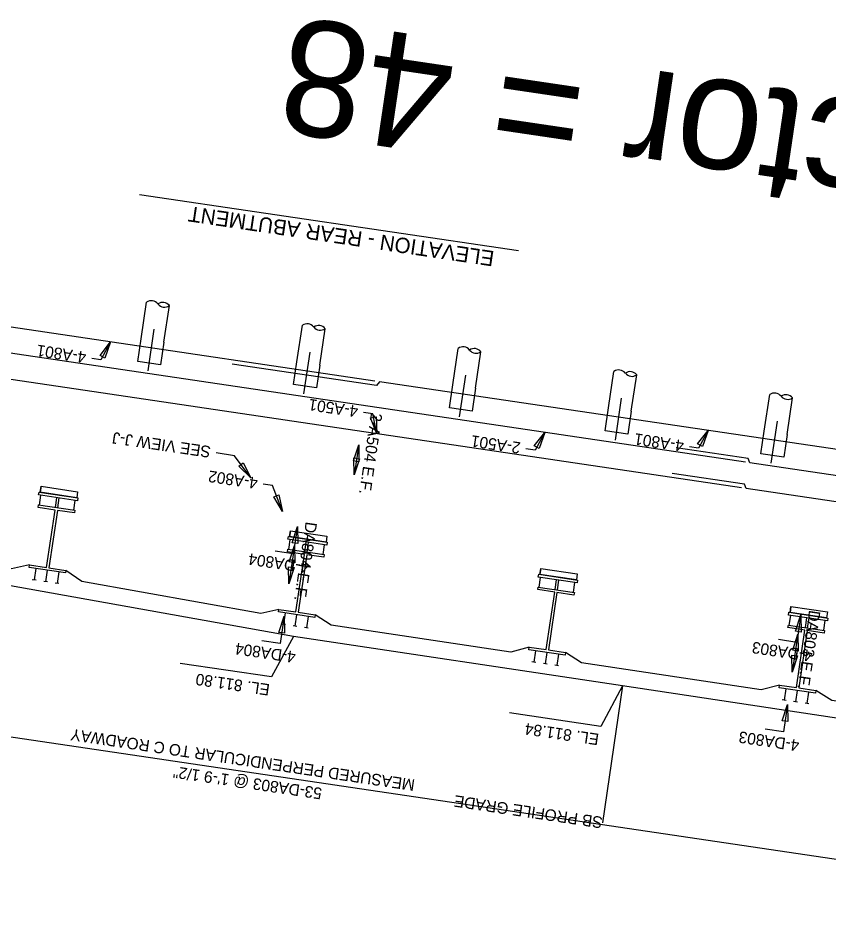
# Model space of a CAD drawing. Extents: x 1468952 to 1470054, y 573916 to 574214.
# Drawn here: x 1469014.75 to 1469049.93, y 574056.5 to 574095.95 of the extents above; entities that cross this region are included whole.
import ezdxf

# ---------------------------------------------------------------- set-up
doc = ezdxf.new("R2010")
doc.units = 0
for name, color, linetype in [('BR_P_Beam_Stl_Det', 7, 'Continuous'), ('BR_P_Gen_Phase_Construction', 7, 'Continuous'), ('BR_P_Sub_Centerline', 7, 'Continuous'), ('BR_P_Sub_Foot_Centerline', 7, 'Continuous'), ('BR_X_SV_Beam_Seat', 7, 'Continuous'), ('Default', 7, 'Continuous'), ('GE_P_CL_50', 7, 'Continuous'), ('GK_Cells', 7, 'Continuous'), ('PF_X_Ground_Line', 7, 'Continuous'), ('SV_X_Text_Elevation', 7, 'Continuous'), ('UT_X_Water', 7, 'Continuous')]:
    doc.layers.add(name, color=color, linetype=linetype)

# ---------------------------------------------------------------- blocks, each defined once
blk = doc.blocks.new('arrowOhio')
at = {"layer": 'Default'}
blk.add_lwpolyline([(0.00381, 0.000635), (0.00381, -0.000635), (0, 0)], close=True, dxfattribs=at)

msp = doc.modelspace()

# ---------------------------------------------------------------- linework, layer by layer
at = {"layer": 'BR_P_Beam_Stl_Det'}
for points in [[(1469030.229, 574080.212), (1469004.495, 574084.021), (1469004.371, 574083.865), (1468998.106, 574084.792)], [(1469046.308, 574076.694), (1469010.886, 574081.938), (1469010.812, 574082.124), (1469007.68, 574082.588)], [(1469046.144, 574075.581), (1469010.721, 574080.825), (1469010.648, 574081.011), (1469007.515, 574081.475)], [(1469056.161, 574076.372), (1469030.427, 574080.182), (1469030.303, 574080.026), (1469024.038, 574080.953)], [(1469082.126, 574071.391), (1469046.506, 574076.665), (1469046.433, 574076.85), (1469043.3, 574077.314)], [(1469081.962, 574070.278), (1469046.341, 574075.552), (1469046.268, 574075.738), (1469043.135, 574076.201)]]:
    msp.add_lwpolyline(points, dxfattribs=at)
at = {"layer": 'BR_P_Gen_Phase_Construction'}
for p, q in [((1469020.089, 574082.05), (1469020.323, 574083.632)), ((1469021.078, 574081.903), (1469021.313, 574083.486)), ((1469026.849, 574081.049), (1469027.083, 574082.632)), ((1469027.838, 574080.902), (1469028.072, 574082.485)), ((1469033.608, 574080.048), (1469033.843, 574081.631)), ((1469034.598, 574079.902), (1469034.832, 574081.484)), ((1469040.368, 574079.047), (1469040.602, 574080.63)), ((1469041.357, 574078.901), (1469041.592, 574080.484)), ((1469047.128, 574078.047), (1469047.362, 574079.629)), ((1469048.117, 574077.9), (1469048.351, 574079.483))]:
    msp.add_line(p, q, dxfattribs=at)
for centre, start, end in [((1469020.532, 574083.336), 37.976, 125.1816), ((1469021.027, 574083.263), 37.976, 125.1816), ((1469021.104, 574083.782), 217.976, 305.1816), ((1469027.292, 574082.335), 37.976, 125.1816), ((1469027.787, 574082.262), 37.976, 125.1816), ((1469027.863, 574082.782), 217.976, 305.1816), ((1469034.052, 574081.335), 37.976, 125.1816), ((1469034.546, 574081.261), 37.976, 125.1816), ((1469034.623, 574081.781), 217.976, 305.1816), ((1469040.811, 574080.334), 37.976, 125.1816), ((1469041.306, 574080.261), 37.976, 125.1816), ((1469041.383, 574080.78), 217.976, 305.1816), ((1469047.571, 574079.333), 37.976, 125.1816), ((1469048.065, 574079.26), 37.976, 125.1816), ((1469048.142, 574079.779), 217.976, 305.1816)]:
    msp.add_arc(centre, 0.362, start, end, dxfattribs=at)
at = {"layer": 'BR_P_Sub_Centerline'}
for p, q in [((1469019.943, 574081.06), (1469020.089, 574082.05)), ((1469021.078, 574081.903), (1469020.932, 574080.914)), ((1469020.932, 574080.914), (1469019.943, 574081.06)), ((1469026.702, 574080.06), (1469026.849, 574081.049)), ((1469027.838, 574080.902), (1469027.692, 574079.913)), ((1469027.692, 574079.913), (1469026.702, 574080.06)), ((1469033.462, 574079.059), (1469033.608, 574080.048)), ((1469034.598, 574079.902), (1469034.451, 574078.913)), ((1469034.451, 574078.913), (1469033.462, 574079.059)), ((1469040.222, 574078.058), (1469040.368, 574079.047)), ((1469041.357, 574078.901), (1469041.211, 574077.912)), ((1469041.211, 574077.912), (1469040.222, 574078.058)), ((1469046.981, 574077.058), (1469047.128, 574078.047)), ((1469048.117, 574077.9), (1469047.97, 574076.911)), ((1469047.97, 574076.911), (1469046.981, 574077.058))]:
    msp.add_line(p, q, dxfattribs=at)
at = {"layer": 'BR_P_Sub_Foot_Centerline'}
for p, q in [((1469015.673, 574074.836), (1469015.736, 574075.259)), ((1469016.37, 574074.733), (1469016.433, 574075.155)), ((1469016.469, 574074.718), (1469016.532, 574075.141)), ((1469017.166, 574074.615), (1469017.229, 574075.038)), ((1469026.492, 574072.911), (1469026.554, 574073.333)), ((1469027.189, 574072.808), (1469027.251, 574073.23)), ((1469027.288, 574072.793), (1469027.35, 574073.216)), ((1469027.985, 574072.69), (1469028.047, 574073.112)), ((1469037.353, 574071.273), (1469037.415, 574071.695)), ((1469038.05, 574071.17), (1469038.112, 574071.592)), ((1469038.149, 574071.155), (1469038.211, 574071.577)), ((1469038.846, 574071.052), (1469038.908, 574071.474)), ((1469048.212, 574069.625), (1469048.275, 574070.047)), ((1469048.909, 574069.521), (1469048.972, 574069.944)), ((1469049.008, 574069.507), (1469049.071, 574069.929)), ((1469049.705, 574069.404), (1469049.768, 574069.826))]:
    msp.add_line(p, q, dxfattribs=at)
at = {"layer": 'BR_X_SV_Beam_Seat'}
msp.add_line((1469040.98, 574066.988), (1469040.101, 574061.053), dxfattribs=at)
at = {"layer": 'GE_P_CL_50'}
for p, q in [((1469015.745, 574075.647), (1469015.707, 574075.389)), ((1469015.639, 574075.273), (1469015.657, 574075.397)), ((1469017.326, 574075.023), (1469015.639, 574075.273)), ((1469015.657, 574075.397), (1469017.344, 574075.147)), ((1469017.333, 574075.412), (1469017.294, 574075.154)), ((1469017.344, 574075.147), (1469017.326, 574075.023)), ((1469026.563, 574073.722), (1469026.525, 574073.464)), ((1469026.457, 574073.348), (1469026.476, 574073.471)), ((1469028.144, 574073.098), (1469026.457, 574073.348)), ((1469026.476, 574073.471), (1469028.163, 574073.222)), ((1469028.151, 574073.487), (1469028.113, 574073.229)), ((1469028.163, 574073.222), (1469028.144, 574073.098)), ((1469037.424, 574072.083), (1469037.386, 574071.826)), ((1469037.318, 574071.71), (1469037.337, 574071.833)), ((1469039.005, 574071.46), (1469037.318, 574071.71)), ((1469037.337, 574071.833), (1469039.024, 574071.583)), ((1469039.012, 574071.848), (1469038.974, 574071.591)), ((1469039.024, 574071.583), (1469039.005, 574071.46)), ((1469048.284, 574070.435), (1469048.246, 574070.178)), ((1469048.178, 574070.061), (1469048.196, 574070.185)), ((1469049.865, 574069.812), (1469048.178, 574070.061)), ((1469048.196, 574070.185), (1469049.883, 574069.935)), ((1469049.872, 574070.2), (1469049.833, 574069.943)), ((1469049.883, 574069.935), (1469049.865, 574069.812))]:
    msp.add_line(p, q, dxfattribs=at)
for points in [[(1469017.333, 574075.412), (1469017.294, 574075.154), (1469015.707, 574075.389), (1469015.745, 574075.647)], [(1469028.151, 574073.487), (1469028.113, 574073.229), (1469026.525, 574073.464), (1469026.563, 574073.722)], [(1469039.012, 574071.848), (1469038.974, 574071.591), (1469037.386, 574071.826), (1469037.424, 574072.083)], [(1469049.872, 574070.2), (1469049.833, 574069.943), (1469048.246, 574070.178), (1469048.284, 574070.435)]]:
    msp.add_lwpolyline(points, close=True, dxfattribs=at)
at = {"layer": 'GK_Cells'}
for p, q in [((1469015.615, 574074.729), (1469015.632, 574074.842)), ((1469015.632, 574074.842), (1469017.207, 574074.609)), ((1469016.353, 574074.62), (1469015.615, 574074.729)), ((1469015.984, 574072.126), (1469016.353, 574074.62)), ((1469016.453, 574074.605), (1469016.083, 574072.111)), ((1469017.191, 574074.496), (1469016.453, 574074.605)), ((1469017.207, 574074.609), (1469017.191, 574074.496)), ((1469026.434, 574072.804), (1469026.451, 574072.917)), ((1469027.172, 574072.694), (1469026.434, 574072.804)), ((1469026.451, 574072.917), (1469028.026, 574072.684)), ((1469026.803, 574070.201), (1469027.172, 574072.694)), ((1469027.271, 574072.68), (1469026.902, 574070.186)), ((1469028.009, 574072.571), (1469027.271, 574072.68)), ((1469028.026, 574072.684), (1469028.009, 574072.571)), ((1469015.229, 574072.122), (1469015.246, 574072.235)), ((1469016.805, 574071.889), (1469015.229, 574072.122)), ((1469015.246, 574072.235), (1469015.984, 574072.126)), ((1469015.522, 574072.078), (1469015.449, 574071.584)), ((1469016.017, 574072.005), (1469015.944, 574071.511)), ((1469016.083, 574072.111), (1469016.821, 574072.002)), ((1469016.821, 574072.002), (1469016.805, 574071.889)), ((1469015.532, 574071.572), (1469015.367, 574071.596)), ((1469016.512, 574071.932), (1469016.438, 574071.437)), ((1469016.026, 574071.498), (1469015.861, 574071.523)), ((1469016.521, 574071.425), (1469016.356, 574071.45)), ((1469037.295, 574071.165), (1469037.312, 574071.279)), ((1469037.312, 574071.279), (1469038.887, 574071.046)), ((1469038.033, 574071.056), (1469037.295, 574071.165)), ((1469037.664, 574068.563), (1469038.033, 574071.056)), ((1469038.132, 574071.042), (1469037.763, 574068.548)), ((1469038.87, 574070.932), (1469038.132, 574071.042)), ((1469038.887, 574071.046), (1469038.87, 574070.932)), ((1469026.048, 574070.197), (1469026.065, 574070.31)), ((1469027.623, 574069.964), (1469026.048, 574070.197)), ((1469026.065, 574070.31), (1469026.803, 574070.201)), ((1469026.341, 574070.153), (1469026.268, 574069.659)), ((1469026.836, 574070.08), (1469026.762, 574069.586)), ((1469026.902, 574070.186), (1469027.64, 574070.077)), ((1469027.64, 574070.077), (1469027.623, 574069.964)), ((1469026.35, 574069.647), (1469026.185, 574069.671)), ((1469027.33, 574070.007), (1469027.257, 574069.512)), ((1469048.154, 574069.517), (1469048.171, 574069.631)), ((1469048.171, 574069.631), (1469049.746, 574069.397)), ((1469026.845, 574069.573), (1469026.68, 574069.598)), ((1469027.339, 574069.5), (1469027.175, 574069.524)), ((1469048.892, 574069.408), (1469048.154, 574069.517)), ((1469048.523, 574066.914), (1469048.892, 574069.408)), ((1469048.992, 574069.393), (1469048.622, 574066.9)), ((1469049.73, 574069.284), (1469048.992, 574069.393)), ((1469049.746, 574069.397), (1469049.73, 574069.284)), ((1469036.909, 574068.558), (1469036.926, 574068.672)), ((1469038.484, 574068.325), (1469036.909, 574068.558)), ((1469036.926, 574068.672), (1469037.664, 574068.563)), ((1469037.202, 574068.515), (1469037.129, 574068.02)), ((1469037.697, 574068.442), (1469037.623, 574067.947)), ((1469037.763, 574068.548), (1469038.501, 574068.439)), ((1469038.501, 574068.439), (1469038.484, 574068.325)), ((1469038.191, 574068.369), (1469038.118, 574067.874)), ((1469037.211, 574068.008), (1469037.046, 574068.033)), ((1469037.706, 574067.935), (1469037.541, 574067.959)), ((1469038.2, 574067.862), (1469038.035, 574067.886)), ((1469047.768, 574066.91), (1469047.785, 574067.024)), ((1469049.344, 574066.677), (1469047.768, 574066.91)), ((1469047.785, 574067.024), (1469048.523, 574066.914)), ((1469048.061, 574066.867), (1469047.988, 574066.372)), ((1469048.622, 574066.9), (1469049.36, 574066.79)), ((1469048.556, 574066.794), (1469048.483, 574066.299)), ((1469049.051, 574066.721), (1469048.977, 574066.226)), ((1469049.36, 574066.79), (1469049.344, 574066.677)), ((1469048.071, 574066.36), (1469047.906, 574066.385)), ((1469048.565, 574066.287), (1469048.4, 574066.311)), ((1469049.06, 574066.214), (1469048.895, 574066.238))]:
    msp.add_line(p, q, dxfattribs=at)
at = {"layer": 'PF_X_Ground_Line'}
for p, q in [((1469026.696, 574069.14), (1468981.648, 574077.187)), ((1469040.98, 574066.988), (1469026.696, 574069.14)), ((1469071.925, 574062.316), (1469040.98, 574066.988))]:
    msp.add_line(p, q, dxfattribs=at)
for points in [[(1469015.246, 574072.235), (1469014.463, 574072.066), (1469006.691, 574073.454), (1469006.004, 574073.937)], [(1469026.065, 574070.31), (1469025.28, 574070.134), (1469017.509, 574071.522), (1469016.821, 574072.002)], [(1469036.926, 574068.672), (1469036.135, 574068.455), (1469028.332, 574069.631), (1469027.64, 574070.077)], [(1469047.785, 574067.024), (1469046.996, 574066.817), (1469039.193, 574067.994), (1469038.501, 574068.439)], [(1469058.646, 574065.385), (1469057.857, 574065.177), (1469050.054, 574066.355), (1469049.36, 574066.79)]]:
    msp.add_lwpolyline(points, dxfattribs=at)
at = {"layer": 'SV_X_Text_Elevation'}
for p, q in [((1469036.469, 574085.858), (1469020.024, 574088.293)), ((1469018.758, 574081.91), (1469018.339, 574081.136)), ((1469018.339, 574081.136), (1469017.943, 574081.194)), ((1469030.136, 574078.787), (1469029.74, 574078.845)), ((1469030.312, 574077.925), (1469030.136, 574078.787)), ((1469037.601, 574077.983), (1469037.182, 574077.209)), ((1469044.69, 574078.071), (1469044.271, 574077.297)), ((1469029.527, 574077.451), (1469029.334, 574076.142)), ((1469037.182, 574077.209), (1469036.787, 574077.268)), ((1469044.271, 574077.297), (1469043.875, 574077.355)), ((1469024.139, 574076.976), (1469023.348, 574077.093)), ((1469024.855, 574076.013), (1469024.139, 574076.976)), ((1469025.783, 574075.677), (1469025.388, 574075.736)), ((1469026.225, 574074.562), (1469025.783, 574075.677)), ((1469026.867, 574073.901), (1469026.691, 574072.714)), ((1469026.691, 574072.714), (1469025.9, 574072.831)), ((1469026.745, 574073.074), (1469026.499, 574071.419)), ((1469070.259, 574056.497), (1468978.025, 574070.152)), ((1469026.292, 574070.015), (1469026.116, 574068.828)), ((1469048.708, 574070.066), (1469048.533, 574068.879)), ((1469048.586, 574069.239), (1469048.341, 574067.584)), ((1469026.116, 574068.828), (1469025.325, 574068.945)), ((1469026.696, 574069.14), (1469025.745, 574067.382)), ((1469048.533, 574068.879), (1469047.741, 574068.996)), ((1469025.745, 574067.382), (1469021.788, 574067.967)), ((1469040.98, 574066.988), (1469040.028, 574065.229)), ((1469048.133, 574066.18), (1469047.957, 574064.993)), ((1469040.028, 574065.229), (1469036.071, 574065.815)), ((1469047.957, 574064.993), (1469047.166, 574065.11))]:
    msp.add_line(p, q, dxfattribs=at)
at = {"layer": 'UT_X_Water'}
for p, q in [((1469020.388, 574080.657), (1469020.657, 574082.471)), ((1469027.148, 574079.657), (1469027.417, 574081.47)), ((1469033.908, 574078.656), (1469034.176, 574080.47)), ((1469040.667, 574077.655), (1469040.936, 574079.469)), ((1469047.427, 574076.655), (1469047.696, 574078.468))]:
    msp.add_line(p, q, dxfattribs=at)

# ---------------------------------------------------------------- block references
at = {"layer": 'SV_X_Text_Elevation'}
for p, xscale, yscale, rotation in [((1469018.758, 574081.91), 191.49567999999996, 191.49568, -118.42123067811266), ((1469030.312, 574077.925), 191.49567999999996, 191.49568, 101.57876932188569), ((1469037.601, 574077.983), 191.49568000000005, 191.49568000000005, -118.42123067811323), ((1469044.69, 574078.071), 191.49568000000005, 191.49568000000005, -118.42123067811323), ((1469029.527, 574077.451), 191.49568000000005, 191.49568, -98.42123067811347), ((1469029.334, 574076.142), 191.49568000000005, 191.49568, 81.57876932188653), ((1469024.855, 574076.013), 191.49568000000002, 191.49568000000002, 126.57876932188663), ((1469026.225, 574074.562), 191.49568000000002, 191.49568000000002, 111.57876932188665), ((1469026.867, 574073.901), 191.49568000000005, 191.49568, -98.42123067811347), ((1469026.745, 574073.074), 191.49568000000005, 191.49568, -98.42123067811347), ((1469026.499, 574071.419), 191.49568000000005, 191.49568, 81.57876932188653), ((1469026.292, 574070.015), 191.49568000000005, 191.49568, -98.42123067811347), ((1469048.708, 574070.066), 191.49568000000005, 191.49568, -98.42123067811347), ((1469048.586, 574069.239), 191.49568000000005, 191.49568, -98.42123067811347), ((1469048.341, 574067.584), 191.49568000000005, 191.49568, 81.57876932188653), ((1469048.133, 574066.18), 191.49568000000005, 191.49568, -98.42123067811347)]:
    msp.add_blockref('arrowOhio', p, dxfattribs=dict(at, xscale=xscale, yscale=yscale, rotation=rotation))

# ---------------------------------------------------------------- texts
for s, height, rotation, p in [('Scale Factor = 48', 4.99999, 171.5788, (1469078.57, 574088.343)), ('ELEVATION - REAR ABUTMENT', 0.665, 171.5788, (1469035.442, 574085.842)), ('4-A801', 0.5, 171.5788, (1469017.732, 574081.478)), ('4-A501', 0.5, 171.5788, (1469029.529, 574079.129)), ('2-A504 E.F.', 0.5, 261.5788, (1469030.066, 574078.861)), ('SEE VIEW J-J', 0.5, 171.5788, (1469023.137, 574077.377)), ('4-A801', 0.5, 171.5788, (1469043.664, 574077.639)), ('2-A501', 0.5, 171.5788, (1469036.576, 574077.551)), ('4-A802', 0.5, 171.5788, (1469025.177, 574076.02)), ('DA804 E.F.', 0.5, 261.5788, (1469027.231, 574074.132)), ('4-DA804', 0.5, 171.5788, (1469027.396, 574072.361)), ('DA803 E.F.', 0.5, 261.5788, (1469049.072, 574070.297)), ('4-DA804', 0.5, 171.5788, (1469026.821, 574068.475)), ('4-DA803', 0.5, 171.5788, (1469049.246, 574068.525)), ('EL. 811.80', 0.5, 171.5788, (1469025.697, 574067.059)), ('EL. 811.84', 0.5, 171.5788, (1469039.98, 574064.907)), ('MEASURED PERPENDICULAR TO C ROADWAY', 0.5, 171.5788, (1469031.992, 574062.924)), ('4-DA803', 0.5, 171.5788, (1469048.671, 574064.639)), ('53-DA803 @ 1\'-9 1/2"', 0.5, 171.5788, (1469027.959, 574062.557)), ('SB PROFILE GRADE ', 0.5, 171.5788, (1469040.138, 574061.3))]:
    msp.add_text(s, height=height, rotation=rotation, dxfattribs=at).set_placement(p)

doc.saveas('drawing.dxf')
